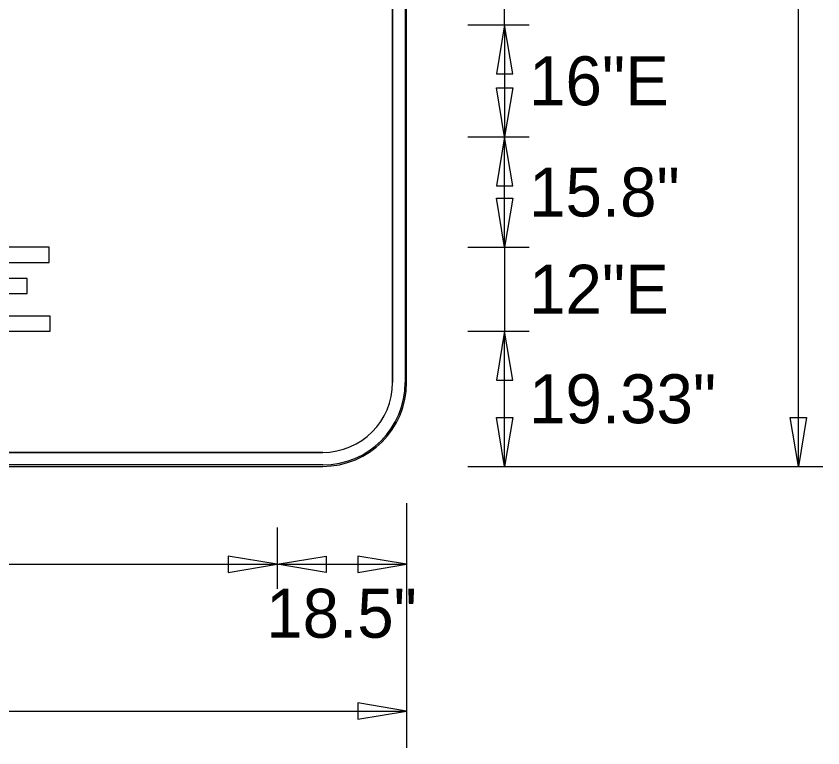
# Model space of a CAD drawing. Extents: x 2149934 to 2150188, y 145114 to 145238.
# Drawn here: x 2150042.37 to 2150051.98, y 145141.03 to 145149.75 of the extents above; entities that cross this region are included whole.
import ezdxf

# ---------------------------------------------------------------- set-up
doc = ezdxf.new("R2010")
doc.units = 0
for name, color, linetype in [('GSBWFILL', 7, 'Continuous'), ('GSCOLORFILL', 7, 'Continuous'), ('GSDIMS', 7, 'Continuous'), ('GSOUTLINE', 7, 'Continuous')]:
    doc.layers.add(name, color=color, linetype=linetype)

msp = doc.modelspace()

# ---------------------------------------------------------------- linework, layer by layer
at = {"layer": 'GSBWFILL'}
for p, q in [((2150046.8532, 145156.3826), (2150046.8532, 145145.3826)), ((2150047.0199, 145145.3826), (2150047.0199, 145156.3826)), ((2150046.0199, 145144.5493), (2150032.5215, 145144.5493)), ((2150032.5215, 145144.3826), (2150046.0199, 145144.3826))]:
    msp.add_line(p, q, dxfattribs=at)
msp.add_lwpolyline([(2150042.7745, 145146.1735), (2150042.2045, 145146.1735), (2150042.2045, 145146.4424), (2150042.4995, 145146.4424), (2150042.4995, 145146.6224), (2150042.2045, 145146.6224), (2150042.2045, 145146.8135), (2150042.7595, 145146.8135), (2150042.7595, 145146.9935), (2150042.0245, 145146.9935), (2150042.0245, 145145.9935), (2150042.7745, 145145.9935)], close=True, dxfattribs=at)
for radius in [1, 0.8333]:
    msp.add_arc((2150046.0199, 145145.3826), radius, 270, 0, dxfattribs=at)
at = {"layer": 'GSCOLORFILL'}
for p, q in [((2150046.8532, 145156.3826), (2150046.8532, 145145.3826)), ((2150047.0032, 145156.3826), (2150047.0032, 145145.3826)), ((2150047.0199, 145145.3826), (2150047.0199, 145156.3826)), ((2150047.0199, 145145.3826), (2150047.0199, 145156.3826)), ((2150047.0199, 145145.3826), (2150047.0199, 145156.3826)), ((2150046.0199, 145144.5493), (2150032.5215, 145144.5493)), ((2150032.5199, 145144.3826), (2150046.0199, 145144.3826)), ((2150046.0199, 145144.3993), (2150032.52, 145144.3993)), ((2150032.52, 145144.3826), (2150046.0199, 145144.3826)), ((2150032.5215, 145144.3826), (2150046.0199, 145144.3826))]:
    msp.add_line(p, q, dxfattribs=at)
msp.add_lwpolyline([(2150042.7745, 145146.1735), (2150042.2045, 145146.1735), (2150042.2045, 145146.4424), (2150042.4995, 145146.4424), (2150042.4995, 145146.6224), (2150042.2045, 145146.6224), (2150042.2045, 145146.8135), (2150042.7595, 145146.8135), (2150042.7595, 145146.9935), (2150042.0245, 145146.9935), (2150042.0245, 145145.9935), (2150042.7745, 145145.9935)], close=True, dxfattribs=at)
for radius in [1, 1, 0.8333, 1, 0.9833]:
    msp.add_arc((2150046.0199, 145145.3826), radius, 270, 0, dxfattribs=at)
at = {"layer": 'GSDIMS'}
for p, q in [((2150048.1866, 145149.6435), (2150048.1866, 145150.6435)), ((2150051.6866, 145144.3826), (2150051.6866, 145150.6435)), ((2150047.7491, 145149.6435), (2150048.4782, 145149.6435)), ((2150047.7491, 145149.6435), (2150048.4782, 145149.6435)), ((2150048.1866, 145149.6435), (2150048.1866, 145148.3101)), ((2150047.7491, 145148.3101), (2150048.4782, 145148.3101)), ((2150047.7491, 145148.3101), (2150048.4782, 145148.3101)), ((2150048.1866, 145146.9935), (2150048.1866, 145148.3101)), ((2150047.7491, 145146.9935), (2150048.4782, 145146.9935)), ((2150047.7491, 145146.9935), (2150048.4782, 145146.9935)), ((2150048.1866, 145146.9935), (2150048.1866, 145145.9935)), ((2150047.7491, 145145.9935), (2150048.4782, 145145.9935)), ((2150047.7491, 145145.9935), (2150048.4782, 145145.9935)), ((2150048.1866, 145144.3826), (2150048.1866, 145145.9935)), ((2150047.7491, 145144.3826), (2150048.4782, 145144.3826)), ((2150047.7491, 145144.3826), (2150051.2491, 145144.3826)), ((2150051.2491, 145144.3826), (2150051.9782, 145144.3826)), ((2150047.0199, 145143.9451), (2150047.0199, 145141.0284)), ((2150045.4783, 145143.6534), (2150045.4783, 145142.9243)), ((2150045.4783, 145143.6534), (2150045.4783, 145142.9243)), ((2150047.0199, 145143.6534), (2150047.0199, 145142.9243)), ((2150033.0614, 145143.2159), (2150045.4783, 145143.2159)), ((2150045.4783, 145143.2159), (2150047.0199, 145143.2159)), ((2150047.0199, 145141.9034), (2150047.0199, 145141.1743)), ((2150031.5198, 145141.4659), (2150047.0199, 145141.4659))]:
    msp.add_line(p, q, dxfattribs=at)
for points in [[(2150048.1866, 145149.6435), (2150048.0893, 145149.0601), (2150048.2838, 145149.0601)], [(2150048.1866, 145148.3101), (2150048.0893, 145148.8935), (2150048.2838, 145148.8935)], [(2150048.1866, 145148.3101), (2150048.0893, 145147.7268), (2150048.2838, 145147.7268)], [(2150048.1866, 145146.9935), (2150048.0893, 145147.5768), (2150048.2838, 145147.5768)], [(2150048.1866, 145145.9935), (2150048.0893, 145145.4101), (2150048.2838, 145145.4101)], [(2150048.1866, 145144.3826), (2150048.0893, 145144.9659), (2150048.2838, 145144.9659)], [(2150051.6866, 145144.3826), (2150051.5893, 145144.9659), (2150051.7838, 145144.9659)], [(2150045.4783, 145143.2159), (2150044.895, 145143.3132), (2150044.895, 145143.1187)], [(2150045.4783, 145143.2159), (2150046.0616, 145143.3132), (2150046.0616, 145143.1187)], [(2150047.0199, 145143.2159), (2150046.4366, 145143.3132), (2150046.4366, 145143.1187)], [(2150047.0199, 145141.4659), (2150046.4366, 145141.5632), (2150046.4366, 145141.3687)]]:
    msp.add_lwpolyline(points, close=True, dxfattribs=at)
at = {"layer": 'GSOUTLINE'}
for p, q in [((2150046.8532, 145145.3826), (2150046.8532, 145156.3826)), ((2150047.0199, 145145.3826), (2150047.0199, 145156.3826)), ((2150032.5199, 145144.5493), (2150046.0199, 145144.5493)), ((2150032.5199, 145144.3826), (2150046.0199, 145144.3826))]:
    msp.add_line(p, q, dxfattribs=at)
msp.add_lwpolyline([(2150042.7745, 145146.1735), (2150042.2045, 145146.1735), (2150042.2045, 145146.4424), (2150042.4995, 145146.4424), (2150042.4995, 145146.6224), (2150042.2045, 145146.6224), (2150042.2045, 145146.8135), (2150042.7595, 145146.8135), (2150042.7595, 145146.9935), (2150042.0245, 145146.9935), (2150042.0245, 145145.9935), (2150042.7745, 145145.9935)], close=True, dxfattribs=at)
for radius in [1, 0.8333]:
    msp.add_arc((2150046.0199, 145145.3826), radius, 270, 0, dxfattribs=at)

# ---------------------------------------------------------------- texts
at = {"layer": 'GSDIMS'}
for s, p in [('16"E', (2150048.4783, 145148.6851)), ('15.8"', (2150048.4783, 145147.3601)), ('12"E', (2150048.4783, 145146.2018)), ('19.33"', (2150048.4783, 145144.8963)), ('18.5"', (2150045.3468, 145142.3409))]:
    msp.add_text(s, height=0.58333, dxfattribs=at).set_placement(p)

doc.saveas('drawing.dxf')
